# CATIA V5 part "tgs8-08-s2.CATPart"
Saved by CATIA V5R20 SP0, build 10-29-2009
Part number: TGS8-08-S2
Revision: 2
Definition: design
Nomenclature: TGS8-08-S2
Source: made
Description: NOT SPECIFIED
Bounding box of the stored display mesh (mm): x -3 to 3, y -8 to 0, z -22 to 0.6
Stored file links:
  C:\Users\Raffaele\Desktop\3D X SITO CF\I-MOLD\TGS-S2\tgs8-s2.step\tgs8-08-s2.CATPart
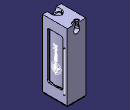
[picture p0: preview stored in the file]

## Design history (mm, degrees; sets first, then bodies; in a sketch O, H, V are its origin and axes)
Set1
  DatumCurve1 "COMPOSITE_CURVE #4071"
  DatumCurve2 "COMPOSITE_CURVE #4117"
  DatumCurve3 "COMPOSITE_CURVE #4350"
  DatumCurve4 "COMPOSITE_CURVE #4410"
  DatumCurve5 "COMPOSITE_CURVE #4467"
  DatumCurve6 "COMPOSITE_CURVE #4628"
  DatumCurve7 "COMPOSITE_CURVE #4655"
  DatumCurve8 "COMPOSITE_CURVE #4682"
  DatumCurve9 "COMPOSITE_CURVE #4765"
  DatumCurve10 "COMPOSITE_CURVE #4816"
  Line1 "LINE #4820": stored without definition
  DatumSurface1 "OPEN_SHELL #4020"
Body1 "MANIFOLD_SOLID_BREP #4021" (main body)
  Solid1: solid without history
